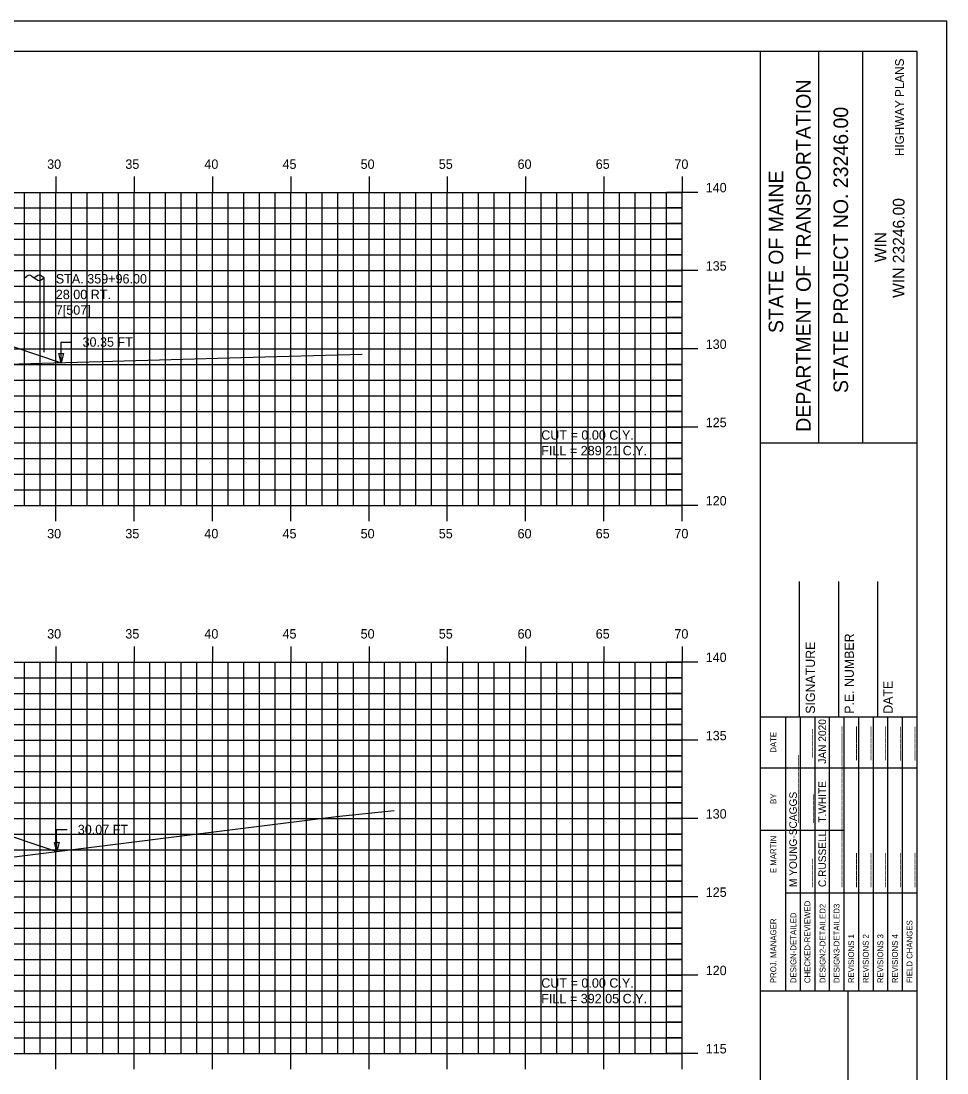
# Model space of a CAD drawing. Extents: x 1146303 to 1146473, y 608981 to 609091.
# Drawn here: x 1146413.7 to 1146472.8, y 609024.1 to 609091.3 of the extents above; entities that cross this region are included whole.
import ezdxf

# ---------------------------------------------------------------- set-up
doc = ezdxf.new("R2010")
doc.units = 0
for name, color, linetype in [('BORDER', 7, 'Continuous'), ('D_Roadway_SlopeLines', 7, 'Continuous'), ('D_Text_Standard', 7, 'Continuous'), ('D_Utilities_Pole_Joint_Rt', 7, 'Continuous'), ('H_V ANNOTATION', 7, 'Continuous'), ('HIGHWAY_TITLE', 7, 'Continuous'), ('MAJOR', 7, 'Continuous'), ('MINOR', 7, 'Continuous'), ('PLOT BOUNDARY', 7, 'Continuous'), ('S_Roadway_Centerline', 7, 'Continuous')]:
    doc.layers.add(name, color=color, linetype=linetype)

msp = doc.modelspace()

# ---------------------------------------------------------------- linework, layer by layer
for points in [[(1146345.732, 609068.815), (1146351.756, 609070.823), (1146354.756, 609071.823), (1146361.905, 609074.206), (1146361.906, 609074.206), (1146374.915, 609074.726), (1146385.915, 609074.946), (1146396.915, 609074.726), (1146400.915, 609074.566), (1146408.638, 609071.992), (1146411.638, 609070.992), (1146416.264, 609069.45)], [(1146344.176, 609035.23), (1146357.382, 609039.632), (1146360.382, 609040.632), (1146367.914, 609043.143), (1146367.915, 609043.143), (1146374.915, 609043.423), (1146385.915, 609043.643), (1146396.915, 609043.423), (1146400.915, 609043.263), (1146408.638, 609040.689), (1146411.638, 609039.689), (1146415.984, 609038.24)]]:
    msp.add_lwpolyline(points)
at = {"layer": 'BORDER'}
for p, q in [((1146460.915, 608984.335), (1146460.915, 609089.335)), ((1146464.643, 609064.332), (1146464.643, 609089.332)), ((1146467.439, 609064.332), (1146467.439, 609089.332)), ((1146460.916, 609064.329), (1146470.915, 609064.329)), ((1146463.415, 609046.838), (1146463.415, 609055.485)), ((1146465.915, 609046.838), (1146465.915, 609055.485)), ((1146468.415, 609046.838), (1146468.415, 609055.485)), ((1146460.915, 609046.838), (1146470.915, 609046.838)), ((1146460.915, 609029.338), (1146470.915, 609029.338)), ((1146466.506, 608994.338), (1146466.506, 609029.338))]:
    msp.add_line(p, q, dxfattribs=at)
msp.add_lwpolyline([(1146310.915, 608984.335), (1146470.915, 608984.335), (1146470.915, 609089.335), (1146310.915, 609089.335)], close=True, dxfattribs=at)
for points in [[(1146462.53, 609043.588), (1146462.53, 609046.838)], [(1146463.462, 609029.341), (1146463.462, 609046.838)], [(1146464.394, 609046.838), (1146464.394, 609029.341)], [(1146465.326, 609029.341), (1146465.326, 609046.838)], [(1146466.257, 609029.341), (1146466.257, 609046.838)], [(1146467.189, 609029.341), (1146467.189, 609046.838)], [(1146468.121, 609029.341), (1146468.121, 609046.838)], [(1146469.052, 609029.341), (1146469.052, 609046.838)], [(1146469.984, 609029.341), (1146469.984, 609046.838)], [(1146462.531, 609029.341), (1146462.531, 609046.132)], [(1146460.915, 609043.588), (1146470.915, 609043.588)], [(1146460.915, 609039.588), (1146462.531, 609039.588)], [(1146462.53, 609039.588), (1146466.256, 609039.588)], [(1146462.53, 609035.588), (1146470.915, 609035.588)]]:
    msp.add_lwpolyline(points, dxfattribs=at)
at = {"layer": 'D_Roadway_SlopeLines'}
for points in [[(1146411.638, 609070.992), (1146416.264, 609069.45)], [(1146411.638, 609039.689), (1146415.984, 609038.24)]]:
    msp.add_lwpolyline(points, dxfattribs=at)
at = {"layer": 'D_Text_Standard'}
for points in [[(1146416.264, 609069.45), (1146416.262, 609070.774), (1146416.942, 609070.774)], [(1146415.984, 609038.24), (1146415.959, 609039.639), (1146416.639, 609039.639)]]:
    msp.add_lwpolyline(points, dxfattribs=at)
for points in [[(1146416.264, 609069.45), (1146416.118, 609070.032), (1146416.409, 609070.032)], [(1146415.984, 609038.24), (1146415.828, 609038.819), (1146416.119, 609038.825)]]:
    msp.add_lwpolyline(points, close=True, dxfattribs=at)
at = {"layer": 'D_Utilities_Pole_Joint_Rt'}
for p, q in [((1146413.915, 609074.875), (1146414.071, 609074.985)), ((1146413.915, 609070.117), (1146413.915, 609074.875)), ((1146414.383, 609074.985), (1146414.539, 609074.875)), ((1146414.696, 609074.985), (1146414.539, 609074.875)), ((1146414.539, 609074.875), (1146414.696, 609074.764)), ((1146415.165, 609074.875), (1146415.009, 609074.985)), ((1146415.009, 609074.764), (1146415.165, 609074.875)), ((1146415.165, 609070.117), (1146415.165, 609074.875))]:
    msp.add_line(p, q, dxfattribs=at)
for centre, start, end in [((1146414.227, 609074.764), 90, 125.26439), ((1146414.227, 609074.764), 54.73561, 90), ((1146414.852, 609074.764), 90, 125.26439), ((1146414.852, 609074.985), 234.73561, 270), ((1146414.852, 609074.764), 54.73561, 90), ((1146414.852, 609074.985), 270, 305.26439)]:
    msp.add_arc(centre, 0.271, start, end, dxfattribs=at)
at = {"layer": 'MAJOR'}
for p, q in [((1146415.915, 609081.337), (1146415.915, 609080.335)), ((1146420.915, 609081.337), (1146420.915, 609080.335)), ((1146425.915, 609081.337), (1146425.915, 609080.335)), ((1146430.915, 609081.337), (1146430.915, 609080.335)), ((1146435.915, 609081.337), (1146435.915, 609080.335)), ((1146440.915, 609081.337), (1146440.915, 609080.335)), ((1146445.915, 609081.337), (1146445.915, 609080.335)), ((1146450.915, 609081.337), (1146450.915, 609080.335)), ((1146455.915, 609081.337), (1146455.915, 609080.335)), ((1146315.915, 609080.335), (1146455.915, 609080.335)), ((1146315.915, 609080.335), (1146455.915, 609080.335)), ((1146415.915, 609060.335), (1146415.915, 609080.335)), ((1146420.915, 609060.335), (1146420.915, 609080.335)), ((1146425.915, 609060.335), (1146425.915, 609080.335)), ((1146430.915, 609060.335), (1146430.915, 609080.335)), ((1146435.915, 609060.335), (1146435.915, 609080.335)), ((1146440.915, 609060.335), (1146440.915, 609080.335)), ((1146445.915, 609060.335), (1146445.915, 609080.335)), ((1146450.915, 609060.335), (1146450.915, 609080.335)), ((1146456.917, 609080.335), (1146454.913, 609080.335)), ((1146455.915, 609060.335), (1146455.915, 609080.335)), ((1146455.915, 609060.335), (1146455.915, 609080.335)), ((1146315.915, 609075.335), (1146455.915, 609075.335)), ((1146456.917, 609075.335), (1146454.913, 609075.335)), ((1146315.915, 609070.335), (1146455.915, 609070.335)), ((1146456.917, 609070.335), (1146454.913, 609070.335)), ((1146315.915, 609065.335), (1146455.915, 609065.335)), ((1146456.917, 609065.335), (1146454.913, 609065.335)), ((1146315.915, 609060.335), (1146455.915, 609060.335)), ((1146315.915, 609060.335), (1146455.915, 609060.335)), ((1146415.915, 609059.333), (1146415.915, 609060.335)), ((1146420.915, 609059.333), (1146420.915, 609060.335)), ((1146425.915, 609059.333), (1146425.915, 609060.335)), ((1146430.915, 609059.333), (1146430.915, 609060.335)), ((1146435.915, 609059.333), (1146435.915, 609060.335)), ((1146440.915, 609059.333), (1146440.915, 609060.335)), ((1146445.915, 609059.333), (1146445.915, 609060.335)), ((1146450.915, 609059.333), (1146450.915, 609060.335)), ((1146456.917, 609060.335), (1146454.913, 609060.335)), ((1146455.915, 609059.333), (1146455.915, 609060.335)), ((1146415.915, 609051.337), (1146415.915, 609050.335)), ((1146420.915, 609051.337), (1146420.915, 609050.335)), ((1146425.915, 609051.337), (1146425.915, 609050.335)), ((1146430.915, 609051.337), (1146430.915, 609050.335)), ((1146435.915, 609051.337), (1146435.915, 609050.335)), ((1146440.915, 609051.337), (1146440.915, 609050.335)), ((1146445.915, 609051.337), (1146445.915, 609050.335)), ((1146450.915, 609051.337), (1146450.915, 609050.335)), ((1146455.915, 609051.337), (1146455.915, 609050.335)), ((1146315.915, 609050.335), (1146455.915, 609050.335)), ((1146315.915, 609050.335), (1146455.915, 609050.335)), ((1146415.915, 609025.335), (1146415.915, 609050.335)), ((1146420.915, 609025.335), (1146420.915, 609050.335)), ((1146425.915, 609025.335), (1146425.915, 609050.335)), ((1146430.915, 609025.335), (1146430.915, 609050.335)), ((1146435.915, 609025.335), (1146435.915, 609050.335)), ((1146440.915, 609025.335), (1146440.915, 609050.335)), ((1146445.915, 609025.335), (1146445.915, 609050.335)), ((1146450.915, 609025.335), (1146450.915, 609050.335)), ((1146456.917, 609050.335), (1146454.913, 609050.335)), ((1146455.915, 609025.335), (1146455.915, 609050.335)), ((1146455.915, 609025.335), (1146455.915, 609050.335)), ((1146315.915, 609045.335), (1146455.915, 609045.335)), ((1146456.917, 609045.335), (1146454.913, 609045.335)), ((1146315.915, 609040.335), (1146455.915, 609040.335)), ((1146456.917, 609040.335), (1146454.913, 609040.335)), ((1146315.915, 609035.335), (1146455.915, 609035.335)), ((1146456.917, 609035.335), (1146454.913, 609035.335)), ((1146315.915, 609030.335), (1146455.915, 609030.335)), ((1146456.917, 609030.335), (1146454.913, 609030.335)), ((1146315.915, 609025.335), (1146455.915, 609025.335)), ((1146315.915, 609025.335), (1146455.915, 609025.335)), ((1146415.915, 609024.333), (1146415.915, 609025.335)), ((1146420.915, 609024.333), (1146420.915, 609025.335)), ((1146425.915, 609024.333), (1146425.915, 609025.335)), ((1146430.915, 609024.333), (1146430.915, 609025.335)), ((1146435.915, 609024.333), (1146435.915, 609025.335)), ((1146440.915, 609024.333), (1146440.915, 609025.335)), ((1146445.915, 609024.333), (1146445.915, 609025.335)), ((1146450.915, 609024.333), (1146450.915, 609025.335)), ((1146456.917, 609025.335), (1146454.913, 609025.335)), ((1146455.915, 609024.333), (1146455.915, 609025.335))]:
    msp.add_line(p, q, dxfattribs=at)
at = {"layer": 'MINOR'}
for p, q in [((1146413.915, 609060.335), (1146413.915, 609080.335)), ((1146414.915, 609060.335), (1146414.915, 609080.335)), ((1146416.915, 609060.335), (1146416.915, 609080.335)), ((1146417.915, 609060.335), (1146417.915, 609080.335)), ((1146418.915, 609060.335), (1146418.915, 609080.335)), ((1146419.915, 609060.335), (1146419.915, 609080.335)), ((1146421.915, 609060.335), (1146421.915, 609080.335)), ((1146422.915, 609060.335), (1146422.915, 609080.335)), ((1146423.915, 609060.335), (1146423.915, 609080.335)), ((1146424.915, 609060.335), (1146424.915, 609080.335)), ((1146426.915, 609060.335), (1146426.915, 609080.335)), ((1146427.915, 609060.335), (1146427.915, 609080.335)), ((1146428.915, 609060.335), (1146428.915, 609080.335)), ((1146429.915, 609060.335), (1146429.915, 609080.335)), ((1146431.915, 609060.335), (1146431.915, 609080.335)), ((1146432.915, 609060.335), (1146432.915, 609080.335)), ((1146433.915, 609060.335), (1146433.915, 609080.335)), ((1146434.915, 609060.335), (1146434.915, 609080.335)), ((1146436.915, 609060.335), (1146436.915, 609080.335)), ((1146437.915, 609060.335), (1146437.915, 609080.335)), ((1146438.915, 609060.335), (1146438.915, 609080.335)), ((1146439.915, 609060.335), (1146439.915, 609080.335)), ((1146441.915, 609060.335), (1146441.915, 609080.335)), ((1146442.915, 609060.335), (1146442.915, 609080.335)), ((1146443.915, 609060.335), (1146443.915, 609080.335)), ((1146444.915, 609060.335), (1146444.915, 609080.335)), ((1146446.915, 609060.335), (1146446.915, 609080.335)), ((1146447.915, 609060.335), (1146447.915, 609080.335)), ((1146448.915, 609060.335), (1146448.915, 609080.335)), ((1146449.915, 609060.335), (1146449.915, 609080.335)), ((1146451.915, 609060.335), (1146451.915, 609080.335)), ((1146452.915, 609060.335), (1146452.915, 609080.335)), ((1146453.915, 609060.335), (1146453.915, 609080.335)), ((1146454.915, 609060.335), (1146454.915, 609080.335)), ((1146315.915, 609079.335), (1146455.915, 609079.335)), ((1146455.915, 609079.335), (1146454.913, 609079.335)), ((1146315.915, 609078.335), (1146455.915, 609078.335)), ((1146455.915, 609078.335), (1146454.913, 609078.335)), ((1146315.915, 609077.335), (1146455.915, 609077.335)), ((1146455.915, 609077.335), (1146454.913, 609077.335)), ((1146315.915, 609076.335), (1146455.915, 609076.335)), ((1146455.915, 609076.335), (1146454.913, 609076.335)), ((1146315.915, 609074.335), (1146455.915, 609074.335)), ((1146455.915, 609074.335), (1146454.913, 609074.335)), ((1146315.915, 609073.335), (1146455.915, 609073.335)), ((1146455.915, 609073.335), (1146454.913, 609073.335)), ((1146315.915, 609072.335), (1146455.915, 609072.335)), ((1146455.915, 609072.335), (1146454.913, 609072.335)), ((1146315.915, 609071.335), (1146455.915, 609071.335)), ((1146455.915, 609071.335), (1146454.913, 609071.335)), ((1146315.915, 609069.335), (1146455.915, 609069.335)), ((1146455.915, 609069.335), (1146454.913, 609069.335)), ((1146315.915, 609068.335), (1146455.915, 609068.335)), ((1146455.915, 609068.335), (1146454.913, 609068.335)), ((1146315.915, 609067.335), (1146455.915, 609067.335)), ((1146455.915, 609067.335), (1146454.913, 609067.335)), ((1146315.915, 609066.335), (1146455.915, 609066.335)), ((1146455.915, 609066.335), (1146454.913, 609066.335)), ((1146315.915, 609064.335), (1146455.915, 609064.335)), ((1146455.915, 609064.335), (1146454.913, 609064.335)), ((1146315.915, 609063.335), (1146455.915, 609063.335)), ((1146455.915, 609063.335), (1146454.913, 609063.335)), ((1146315.915, 609062.335), (1146455.915, 609062.335)), ((1146455.915, 609062.335), (1146454.913, 609062.335)), ((1146315.915, 609061.335), (1146455.915, 609061.335)), ((1146455.915, 609061.335), (1146454.913, 609061.335)), ((1146413.915, 609025.335), (1146413.915, 609050.335)), ((1146414.915, 609025.335), (1146414.915, 609050.335)), ((1146416.915, 609025.335), (1146416.915, 609050.335)), ((1146417.915, 609025.335), (1146417.915, 609050.335)), ((1146418.915, 609025.335), (1146418.915, 609050.335)), ((1146419.915, 609025.335), (1146419.915, 609050.335)), ((1146421.915, 609025.335), (1146421.915, 609050.335)), ((1146422.915, 609025.335), (1146422.915, 609050.335)), ((1146423.915, 609025.335), (1146423.915, 609050.335)), ((1146424.915, 609025.335), (1146424.915, 609050.335)), ((1146426.915, 609025.335), (1146426.915, 609050.335)), ((1146427.915, 609025.335), (1146427.915, 609050.335)), ((1146428.915, 609025.335), (1146428.915, 609050.335)), ((1146429.915, 609025.335), (1146429.915, 609050.335)), ((1146431.915, 609025.335), (1146431.915, 609050.335)), ((1146432.915, 609025.335), (1146432.915, 609050.335)), ((1146433.915, 609025.335), (1146433.915, 609050.335)), ((1146434.915, 609025.335), (1146434.915, 609050.335)), ((1146436.915, 609025.335), (1146436.915, 609050.335)), ((1146437.915, 609025.335), (1146437.915, 609050.335)), ((1146438.915, 609025.335), (1146438.915, 609050.335)), ((1146439.915, 609025.335), (1146439.915, 609050.335)), ((1146441.915, 609025.335), (1146441.915, 609050.335)), ((1146442.915, 609025.335), (1146442.915, 609050.335)), ((1146443.915, 609025.335), (1146443.915, 609050.335)), ((1146444.915, 609025.335), (1146444.915, 609050.335)), ((1146446.915, 609025.335), (1146446.915, 609050.335)), ((1146447.915, 609025.335), (1146447.915, 609050.335)), ((1146448.915, 609025.335), (1146448.915, 609050.335)), ((1146449.915, 609025.335), (1146449.915, 609050.335)), ((1146451.915, 609025.335), (1146451.915, 609050.335)), ((1146452.915, 609025.335), (1146452.915, 609050.335)), ((1146453.915, 609025.335), (1146453.915, 609050.335)), ((1146454.915, 609025.335), (1146454.915, 609050.335)), ((1146315.915, 609049.335), (1146455.915, 609049.335)), ((1146455.915, 609049.335), (1146454.913, 609049.335)), ((1146315.915, 609048.335), (1146455.915, 609048.335)), ((1146455.915, 609048.335), (1146454.913, 609048.335)), ((1146315.915, 609047.335), (1146455.915, 609047.335)), ((1146455.915, 609047.335), (1146454.913, 609047.335)), ((1146315.915, 609046.335), (1146455.915, 609046.335)), ((1146455.915, 609046.335), (1146454.913, 609046.335)), ((1146315.915, 609044.335), (1146455.915, 609044.335)), ((1146455.915, 609044.335), (1146454.913, 609044.335)), ((1146315.915, 609043.335), (1146455.915, 609043.335)), ((1146455.915, 609043.335), (1146454.913, 609043.335)), ((1146315.915, 609042.335), (1146455.915, 609042.335)), ((1146455.915, 609042.335), (1146454.913, 609042.335)), ((1146315.915, 609041.335), (1146455.915, 609041.335)), ((1146455.915, 609041.335), (1146454.913, 609041.335)), ((1146315.915, 609039.335), (1146455.915, 609039.335)), ((1146455.915, 609039.335), (1146454.913, 609039.335)), ((1146315.915, 609038.335), (1146455.915, 609038.335)), ((1146455.915, 609038.335), (1146454.913, 609038.335)), ((1146315.915, 609037.335), (1146455.915, 609037.335)), ((1146455.915, 609037.335), (1146454.913, 609037.335)), ((1146315.915, 609036.335), (1146455.915, 609036.335)), ((1146455.915, 609036.335), (1146454.913, 609036.335)), ((1146315.915, 609034.335), (1146455.915, 609034.335)), ((1146455.915, 609034.335), (1146454.913, 609034.335)), ((1146315.915, 609033.335), (1146455.915, 609033.335)), ((1146455.915, 609033.335), (1146454.913, 609033.335)), ((1146315.915, 609032.335), (1146455.915, 609032.335)), ((1146455.915, 609032.335), (1146454.913, 609032.335)), ((1146315.915, 609031.335), (1146455.915, 609031.335)), ((1146455.915, 609031.335), (1146454.913, 609031.335)), ((1146315.915, 609029.335), (1146455.915, 609029.335)), ((1146455.915, 609029.335), (1146454.913, 609029.335)), ((1146315.915, 609028.335), (1146455.915, 609028.335)), ((1146455.915, 609028.335), (1146454.913, 609028.335)), ((1146315.915, 609027.335), (1146455.915, 609027.335)), ((1146455.915, 609027.335), (1146454.913, 609027.335)), ((1146315.915, 609026.335), (1146455.915, 609026.335)), ((1146455.915, 609026.335), (1146454.913, 609026.335))]:
    msp.add_line(p, q, dxfattribs=at)
at = {"layer": 'PLOT BOUNDARY'}
msp.add_lwpolyline([(1146302.822, 608981.276), (1146472.822, 608981.276), (1146472.822, 609091.276), (1146302.822, 609091.276)], close=True, dxfattribs=at)
at = {"layer": 'S_Roadway_Centerline'}
for points in [[(1146335.721, 609068.741), (1146341.913, 609068.95), (1146350.501, 609068.647), (1146356.167, 609069.121), (1146361.353, 609069.451), (1146366.347, 609070.038), (1146369.93, 609070.733), (1146371.977, 609070.829), (1146373.05, 609070.897), (1146381.577, 609071.163), (1146383.909, 609071.217), (1146392.607, 609070.964), (1146394.83, 609070.89), (1146395.634, 609070.833), (1146398.837, 609070.419), (1146399.625, 609070.062), (1146402.46, 609069.28), (1146409.532, 609069.264), (1146410.109, 609069.369), (1146413.555, 609069.372), (1146429.262, 609069.823), (1146435.475, 609069.99)], [(1146333.388, 609034.911), (1146346.209, 609035.291), (1146349.129, 609035.414), (1146357.59, 609036.333), (1146359.818, 609036.527), (1146361.268, 609036.808), (1146369.098, 609038.216), (1146370.961, 609038.37), (1146372.738, 609038.608), (1146374.647, 609038.666), (1146383.693, 609038.936), (1146385.688, 609038.859), (1146395.034, 609038.539), (1146397.895, 609038.178), (1146398.57, 609038.098), (1146401.631, 609036.957), (1146404.946, 609035.238), (1146408.835, 609036.389), (1146410.172, 609037.511), (1146433.848, 609040.479), (1146437.527, 609040.851)]]:
    msp.add_lwpolyline(points, dxfattribs=at)

# ---------------------------------------------------------------- texts
at = {"layer": 'BORDER'}
for s, height, p in [('DEPARTMENT OF TRANSPORTATION', 0.93176, (1146464.122, 609065.041)), ('STATE PROJECT NO. 23246.00', 0.93176, (1146466.507, 609067.517)), ('STATE OF MAINE', 0.93176, (1146462.37, 609071.347)), ('WIN 23246.00', 0.74527, (1146470.11, 609073.596)), ('WIN', 0.7453, (1146468.952, 609075.865)), ('P.E. NUMBER', 0.59055, (1146466.876, 609047.03)), ('SIGNATURE', 0.5906, (1146464.395, 609047.03)), ('DATE', 0.5906, (1146469.356, 609047.03)), ('JAN 2020', 0.4845, (1146465.101, 609043.843)), ('DATE', 0.3714, (1146461.919, 609044.544)), ('_____', 0.4845, (1146464.132, 609044.243)), ('______', 0.4845, (1146465.996, 609044.063)), ('______', 0.4845, (1146466.927, 609044.065)), ('______', 0.4845, (1146467.859, 609044.067)), ('______', 0.4845, (1146468.791, 609044.067)), ('______', 0.4845, (1146469.722, 609044.036)), ('______', 0.4845, (1146470.654, 609044.036)), ('____________', 0.48455, (1146463.238, 609040.073)), ('____________', 0.48455, (1146465.996, 609040.073)), ('T.WHITE', 0.4845, (1146465.101, 609040.073)), ('BY', 0.3714, (1146461.919, 609041.273)), ('M YOUNG-SCAGGS', 0.48455, (1146463.238, 609035.961)), ('_____', 0.4845, (1146464.17, 609040.073)), ('____________', 0.48455, (1146465.996, 609035.961)), ('E MARTIN', 0.3727, (1146461.919, 609036.855)), ('C.RUSSELL', 0.4845, (1146465.101, 609035.961)), ('_____', 0.4845, (1146464.132, 609035.961)), ('______', 0.4845, (1146466.927, 609035.961)), ('______', 0.4845, (1146467.859, 609035.961)), ('______', 0.4845, (1146468.791, 609035.961)), ('______', 0.4845, (1146469.722, 609035.961)), ('______', 0.4845, (1146470.654, 609035.961)), ('CHECKED-REVIEWED', 0.37275, (1146464.096, 609029.826)), ('DESIGN2-DETAILED2', 0.37275, (1146465.065, 609029.826)), ('DESIGN3-DETAILED3', 0.37275, (1146465.959, 609029.826)), ('DESIGN-DETAILED', 0.37275, (1146463.201, 609029.826)), ('PROJ. MANAGER', 0.37275, (1146461.919, 609029.826)), ('FIELD CHANGES', 0.37275, (1146470.618, 609029.826)), ('REVISIONS 1', 0.37275, (1146466.891, 609029.826)), ('REVISIONS 2', 0.37275, (1146467.823, 609029.826)), ('REVISIONS 3', 0.37275, (1146468.754, 609029.826)), ('REVISIONS 4', 0.37275, (1146469.686, 609029.826))]:
    msp.add_text(s, height=height, rotation=90, dxfattribs=at).set_placement(p)
at = {"layer": 'D_Text_Standard'}
for s, p in [('STA. 359+96.00', (1146415.915, 609074.515)), ('28.00 RT.', (1146415.915, 609073.513)), ('7[507] ', (1146415.915, 609072.517)), ('30.35 FT', (1146417.622, 609070.474)), ('CUT = 0.00 C.Y.', (1146446.915, 609064.535)), ('FILL = 289.21 C.Y.', (1146446.915, 609063.539)), ('30.07 FT', (1146417.319, 609039.339)), ('CUT = 0.00 C.Y.', (1146446.915, 609029.535)), ('FILL = 392.05 C.Y.', (1146446.915, 609028.539))]:
    msp.add_text(s, height=0.6, dxfattribs=at).set_placement(p)
at = {"layer": 'H_V ANNOTATION'}
for s, p in [('30', (1146415.363, 609081.835)), ('35', (1146420.355, 609081.835)), ('40', (1146425.401, 609081.835)), ('45', (1146430.393, 609081.835)), ('50', (1146435.379, 609081.835)), ('55', (1146440.371, 609081.835)), ('60', (1146445.401, 609081.835)), ('65', (1146450.393, 609081.835)), ('70', (1146455.417, 609081.835)), ('140', (1146457.415, 609080.335)), ('135', (1146457.415, 609075.335)), ('130', (1146457.415, 609070.335)), ('125', (1146457.415, 609065.335)), ('120', (1146457.415, 609060.335)), ('30', (1146415.363, 609058.235)), ('35', (1146420.355, 609058.235)), ('40', (1146425.401, 609058.235)), ('45', (1146430.393, 609058.235)), ('50', (1146435.379, 609058.235)), ('55', (1146440.371, 609058.235)), ('60', (1146445.401, 609058.235)), ('65', (1146450.393, 609058.235)), ('70', (1146455.417, 609058.235)), ('30', (1146415.363, 609051.835)), ('35', (1146420.355, 609051.835)), ('40', (1146425.401, 609051.835)), ('45', (1146430.393, 609051.835)), ('50', (1146435.379, 609051.835)), ('55', (1146440.371, 609051.835)), ('60', (1146445.401, 609051.835)), ('65', (1146450.393, 609051.835)), ('70', (1146455.417, 609051.835)), ('140', (1146457.415, 609050.335)), ('135', (1146457.415, 609045.335)), ('130', (1146457.415, 609040.335)), ('125', (1146457.415, 609035.335)), ('120', (1146457.415, 609030.335)), ('115', (1146457.415, 609025.335))]:
    msp.add_text(s, height=0.6, dxfattribs=at).set_placement(p)
at = {"layer": 'HIGHWAY_TITLE'}
msp.add_text('HIGHWAY PLANS', height=0.55901, rotation=90, dxfattribs=at).set_placement((1146470.073, 609082.65))

doc.saveas('drawing.dxf')
